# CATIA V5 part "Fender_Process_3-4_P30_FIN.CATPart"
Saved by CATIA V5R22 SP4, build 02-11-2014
Part number: Fender
Bounding box of the stored display mesh (mm): x -800 to 0, y 0 to 122.298, z 0 to 580
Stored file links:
  C:\DATA\Car_ASSY\教育モデル\3_SOL\Fender_Process_3-4_P30_FIN.CATPart
  C:\DATA\Car_ASSY\教育モデル\3_SOL\Car_Fender.CATPart
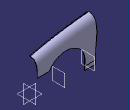
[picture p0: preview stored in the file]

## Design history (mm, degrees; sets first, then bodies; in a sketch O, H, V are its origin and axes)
Set1
  Plane1: type Offset, RefPlane yz-plane, Offset 400, reversed
  Plane2: type Offset, RefPlane Plane1, Offset 400, reversed
Body1 (main body)
Body2
  Sketch1 on yz-plane, origin (0, 0, 0), H (0, 1, 0), V (0, 0, 1)
    point P4 (100, 50)
    point P5 (10, 450)
    spline S1 through (10, 450) (100, 50)
    line L1 (0, 450) -> (10, 450)
    line L2 (0, 0) -> (0, 450)
    line L3 (100, 0) -> (0, 0)
    line L4 (100, 50) -> (100, 0)
    point P6 (100, 50)
    point P7 (10, 450)
    distance P4 L3 = 50
    distance P5 L2 = 10
    distance L4 L2 = 100
    distance L1 H = 450
    coincidence: L2 V, H L3, P4 P6, P7 P5
  Sketch2 on Plane1, origin (-400, 0, 0), H (0, 1, 0), V (0, 0, 1)
    point P4 (100, 50)
    point P5 (10, 530)
    spline S1 through (10, 530) (100, 50)
    line L1 (0, 530) -> (10, 530)
    line L2 (0, 0) -> (0, 530)
    line L3 (100, 0) -> (0, 0)
    line L4 (100, 50) -> (100, 0)
    point P6 (100, 50)
    point P7 (10, 530)
    distance P4 L3 = 50
    distance P5 L2 = 10
    distance L4 L2 = 100
    distance L1 H = 530
    coincidence: L2 V, H L3, P4 P6, P7 P5
  Sketch3 on Plane2, origin (-800, 0, 0), H (0, 1, 0), V (0, 0, 1)
    point P4 (100, 50)
    point P5 (10, 580)
    spline S1 through (10, 580) (100, 50)
    line L1 (0, 580) -> (10, 580)
    line L2 (0, 0) -> (0, 580)
    line L3 (100, 0) -> (0, 0)
    line L4 (100, 50) -> (100, 0)
    point P6 (100, 50)
    point P7 (10, 580)
    distance P4 L3 = 50
    distance P5 L2 = 10
    distance L4 L2 = 100
    distance L1 H = 580
    coincidence: L2 V, H L3, P4 P6, P7 P5
  Loft1: solid, Sections (Sketch1; Sketch2; Sketch3)
  Body3
    Sketch4 on zx-plane, origin (0, 0, 0), H (-1, 0, 0), V (0, 0, 1)
      line L1 (-46.4952, 240) -> (159.0779, 240)
      arc A1 centre (390, 110) radius 265 from (159.0779, 240) to (655, 109.9999) cw
      point P2 (390, 110)
      line L2 (655, 109.9999) -> (655, -30)
      line L3 (-46.4952, 626.6258) -> (850, 626.6258)
      line L4 (850, 626.6258) -> (850, -30)
      line L5 (850, -30) -> (655, -30)
      line L6 (-46.4952, 626.6258) -> (-46.4952, 240)
      radius A1 = 265
      distance P2 H = 110
      distance V P2 = 390
      distance H L1 = 240
      horizontal: L1 H, L3 H, L5 H
      tangency: L2 A1
      vertical: L2 V, L4 V, L6 V
    Pad1: profile Sketch4, direction (0, 1, 0), length 340, mirrored extent
  Intersect1: tool Body3
  Shell1: ExtOffset 0, Face (face of Loft1; face of Loft1; face of Pad1 from Sketch4.A1; face of Pad1 from Sketch4.L1; face of Loft1; face of Loft1), IntOffset 3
